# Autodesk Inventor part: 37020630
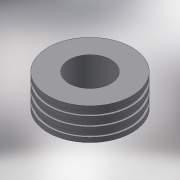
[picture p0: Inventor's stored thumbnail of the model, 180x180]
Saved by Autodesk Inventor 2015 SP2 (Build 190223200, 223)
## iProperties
Created: 2017-08
Part Number: 37020630
Material: Generic
Description: PLASSON MAN HOLE ADAPTOR 630
Document SubType Name: Modeling
Designer: Кирилл
Density: 1 g/cm^3
Appearance: Default
Author: Кирилл
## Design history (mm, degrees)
derived "37020-477207.ipt"
feature "Solid1::37020-477207.ipt"
tag "TaggingFeature1"
body "Solid1"
other parameters: "d0" = 135, "d1" = 773, "d2" = 734.35, "d3" = 555, "L_" = 135, "d_1" = 555, "D_" = 773
